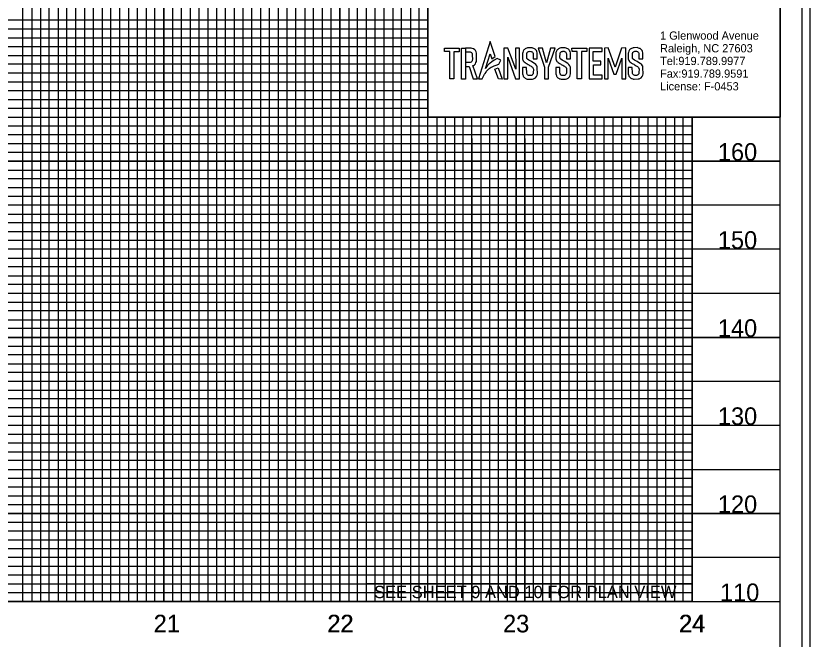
# Model space of a CAD drawing. Extents: x 1779926 to 1781610, y 602514 to 621564.
# Drawn here: x 1781159 to 1781610, y 603068.1 to 603422 of the extents above; entities that cross this region are included whole.
import ezdxf

# ---------------------------------------------------------------- set-up
doc = ezdxf.new("R2010")
doc.units = 0
for name, color, linetype in [('Exist Vertical Profile Horizontal Axis Label Major', 7, 'Continuous'), ('Exist Vertical Profile Vertical Axis Label', 7, 'Continuous'), ('Old_Level_2', 7, 'Continuous'), ('Old_Level_58', 7, 'Continuous'), ('Prop DSN Text', 7, 'Continuous'), ('Prop Grid Mask', 7, 'Continuous'), ('Scratch_Level_0', 7, 'Continuous'), ('Sheet DOT Grid CELL', 7, 'Continuous'), ('Sheet Layout Profile Border Port 1', 7, 'Continuous'), ('Sheet Plot Border Inside CELL', 7, 'Continuous'), ('Sheet Plot Border Outside CELL', 7, 'Continuous'), ('Sheet Profile CELL', 7, 'Continuous'), ('Sheet Profile Grid Major CELL', 7, 'Continuous'), ('Sheet Profile Grid Middle CELL', 7, 'Continuous'), ('Sheet Profile Grid Minor CELL', 7, 'Continuous')]:
    doc.layers.add(name, color=color, linetype=linetype)

msp = doc.modelspace()

# ---------------------------------------------------------------- linework, layer by layer
at = {"layer": 'Old_Level_2'}
for points in [[(1781428.25, 603407.49), (1781421.58, 603386.15), (1781423.81, 603386.16), (1781424.15, 603387), (1781424.72, 603388.16), (1781425.03, 603388.79), (1781425.41, 603389.33), (1781425.93, 603390.09), (1781426.26, 603390.56), (1781426.64, 603390.95), (1781427.02, 603391.34), (1781427.51, 603391.84), (1781427.92, 603392.11), (1781428.33, 603392.44), (1781428.89, 603392.76), (1781429.38, 603393.04), (1781430.6, 603393.61), (1781431.6, 603394.02), (1781433.24, 603394.58), (1781434.38, 603396.72), (1781432.2, 603397.68), (1781430.57, 603396.79), (1781429.19, 603395.89), (1781428.21, 603395.09), (1781427.69, 603394.67), (1781427.15, 603394.1), (1781426.62, 603393.53), (1781426.22, 603393.11), (1781425.84, 603392.46), (1781425.63, 603392.1), (1781428.26, 603400.48), (1781429.26, 603397.59), (1781431.16, 603398.84)], [(1781402.29, 603403.64), (1781410.75, 603403.65), (1781410.75, 603401.57), (1781407.64, 603401.57), (1781407.66, 603386.15), (1781405.31, 603386.15), (1781405.29, 603401.67), (1781402.32, 603401.67)], [(1781411.91, 603403.63), (1781414.22, 603403.64), (1781414.24, 603386.07), (1781411.92, 603386.07)], [(1781414.22, 603401.55), (1781416.61, 603401.55), (1781416.91, 603401.5), (1781417.32, 603401.34), (1781417.64, 603401.12), (1781417.87, 603400.85), (1781418.03, 603400.52), (1781418.15, 603400.26), (1781418.15, 603399.68), (1781418.16, 603397.19), (1781418.1, 603396.86), (1781418.01, 603396.42), (1781417.88, 603396.12), (1781417.68, 603395.86), (1781417.41, 603395.65), (1781416.99, 603395.5), (1781416.66, 603395.45), (1781416.34, 603395.41), (1781414.23, 603395.4), (1781414.24, 603393.29), (1781416.35, 603393.31), (1781418.72, 603386.14), (1781421.13, 603386.17), (1781418.48, 603393.71), (1781418.86, 603393.84), (1781419.4, 603394.24), (1781419.89, 603394.78), (1781420.23, 603395.41), (1781420.45, 603396.04), (1781420.43, 603396.23), (1781420.48, 603400.79), (1781420.27, 603401.54), (1781419.91, 603402.22), (1781419.5, 603402.69), (1781418.8, 603403.16), (1781418.12, 603403.39), (1781417.45, 603403.61), (1781417.04, 603403.61), (1781414.22, 603403.64)], [(1781436.02, 603403.67), (1781436.03, 603386.21), (1781438.27, 603386.21), (1781438.26, 603398.49), (1781442.71, 603386.19), (1781444.96, 603386.22), (1781444.94, 603403.72), (1781442.76, 603403.72), (1781442.78, 603391.74), (1781438.37, 603403.68)], [(1781452.72, 603397.5), (1781455.03, 603397.5), (1781455.02, 603400.98), (1781454.83, 603401.68), (1781454.55, 603402.27), (1781454.25, 603402.66), (1781453.88, 603403.02), (1781453.44, 603403.3), (1781453.01, 603403.47), (1781453.01, 603403.47), (1781452.55, 603403.67), (1781452.07, 603403.79), (1781451.75, 603403.87), (1781450, 603403.83), (1781449.47, 603403.74), (1781449.02, 603403.66), (1781448.55, 603403.42), (1781448.15, 603403.21), (1781447.76, 603402.93), (1781447.45, 603402.61), (1781447.2, 603402.25), (1781447.01, 603401.85), (1781446.75, 603401.16), (1781446.7, 603400.64), (1781446.7, 603397.47), (1781446.82, 603397), (1781447.05, 603396.5), (1781447.34, 603396.09), (1781447.63, 603395.78), (1781448.08, 603395.43), (1781448.54, 603395.09), (1781448.82, 603394.87), (1781449.3, 603394.64), (1781449.79, 603394.42), (1781450.18, 603394.16), (1781450.62, 603393.88), (1781451.15, 603393.61), (1781451.58, 603393.39), (1781452.01, 603393.08), (1781452.32, 603392.78), (1781452.57, 603392.54), (1781452.72, 603392.06), (1781452.82, 603391.76), (1781452.78, 603389.53), (1781452.62, 603389.04), (1781452.38, 603388.62), (1781452.05, 603388.33), (1781451.69, 603388.17), (1781451.35, 603388.1), (1781450.39, 603388.08), (1781450.07, 603388.17), (1781449.74, 603388.36), (1781449.41, 603388.56), (1781449.27, 603388.89), (1781449.13, 603389.23), (1781449.01, 603389.49), (1781448.98, 603392.61), (1781446.64, 603392.58), (1781446.68, 603388.87), (1781446.8, 603388.59), (1781447.07, 603387.72), (1781447.24, 603387.43), (1781447.5, 603387.11), (1781447.88, 603386.74), (1781448.18, 603386.55), (1781448.62, 603386.36), (1781448.78, 603386.3), (1781449.2, 603386.12), (1781449.74, 603386.06), (1781450.13, 603386.02), (1781452.27, 603386.08), (1781452.87, 603386.22), (1781453.69, 603386.59), (1781453.97, 603386.72), (1781454.6, 603387.51), (1781454.93, 603388.3), (1781455.08, 603389.01), (1781455.03, 603392.43), (1781455.02, 603392.9), (1781454.89, 603393.28), (1781454.7, 603393.63), (1781454.16, 603394.39), (1781453.45, 603394.95), (1781452.48, 603395.53), (1781451.73, 603395.97), (1781450.27, 603396.74), (1781449.52, 603397.3), (1781449.19, 603397.72), (1781449.11, 603398), (1781449.03, 603398.29), (1781449.08, 603400.72), (1781449.2, 603400.97), (1781449.33, 603401.23), (1781449.51, 603401.38), (1781449.74, 603401.58), (1781450, 603401.68), (1781450.25, 603401.79), (1781450.4, 603401.76), (1781450.42, 603401.84), (1781451.38, 603401.82), (1781451.65, 603401.71), (1781451.93, 603401.6), (1781452.21, 603401.49), (1781452.34, 603401.3), (1781452.52, 603401.02), (1781452.61, 603400.74), (1781452.71, 603400.47), (1781452.7, 603400.16)], [(1781457.99, 603403.68), (1781455.45, 603403.68), (1781459.07, 603392.8), (1781459.1, 603386.25), (1781461.49, 603386.27), (1781461.46, 603392.76), (1781465.12, 603403.72), (1781462.62, 603403.65), (1781460.31, 603395.31)], [(1781471.59, 603397.52), (1781473.9, 603397.52), (1781473.89, 603401), (1781473.7, 603401.7), (1781473.42, 603402.29), (1781473.12, 603402.68), (1781472.75, 603403.03), (1781472.31, 603403.32), (1781471.88, 603403.49), (1781471.88, 603403.49), (1781471.43, 603403.68), (1781470.94, 603403.81), (1781470.62, 603403.89), (1781468.87, 603403.85), (1781468.34, 603403.76), (1781467.89, 603403.68), (1781467.43, 603403.44), (1781467.02, 603403.23), (1781466.63, 603402.94), (1781466.32, 603402.63), (1781466.08, 603402.27), (1781465.88, 603401.87), (1781465.63, 603401.17), (1781465.58, 603400.66), (1781465.58, 603397.49), (1781465.69, 603397.01), (1781465.92, 603396.52), (1781466.21, 603396.11), (1781466.51, 603395.8), (1781466.96, 603395.45), (1781467.41, 603395.1), (1781467.69, 603394.88), (1781468.18, 603394.66), (1781468.66, 603394.43), (1781469.05, 603394.18), (1781469.49, 603393.89), (1781470.02, 603393.63), (1781470.45, 603393.41), (1781470.88, 603393.09), (1781471.19, 603392.8), (1781471.44, 603392.56), (1781471.59, 603392.08), (1781471.69, 603391.78), (1781471.65, 603389.54), (1781471.49, 603389.06), (1781471.25, 603388.64), (1781470.92, 603388.35), (1781470.56, 603388.19), (1781470.22, 603388.12), (1781469.26, 603388.1), (1781468.94, 603388.19), (1781468.61, 603388.38), (1781468.28, 603388.57), (1781468.14, 603388.91), (1781468, 603389.24), (1781467.88, 603389.51), (1781467.85, 603392.62), (1781465.51, 603392.6), (1781465.55, 603388.89), (1781465.67, 603388.6), (1781465.94, 603387.74), (1781466.12, 603387.45), (1781466.37, 603387.13), (1781466.75, 603386.76), (1781467.05, 603386.56), (1781467.49, 603386.38), (1781467.65, 603386.31), (1781468.08, 603386.13), (1781468.61, 603386.08), (1781469, 603386.04), (1781471.15, 603386.1), (1781471.74, 603386.24), (1781472.57, 603386.61), (1781472.85, 603386.74), (1781473.47, 603387.53), (1781473.8, 603388.31), (1781473.96, 603389.02), (1781473.9, 603392.45), (1781473.9, 603392.92), (1781473.76, 603393.29), (1781473.57, 603393.65), (1781473.03, 603394.41), (1781472.33, 603394.96), (1781471.35, 603395.54), (1781470.61, 603395.99), (1781469.14, 603396.75), (1781468.39, 603397.32), (1781468.06, 603397.74), (1781467.98, 603398.02), (1781467.91, 603398.31), (1781467.95, 603400.74), (1781468.08, 603400.99), (1781468.2, 603401.25), (1781468.38, 603401.4), (1781468.61, 603401.59), (1781468.87, 603401.7), (1781469.13, 603401.81), (1781469.27, 603401.78), (1781469.29, 603401.85), (1781470.25, 603401.84), (1781470.52, 603401.73), (1781470.8, 603401.62), (1781471.08, 603401.51), (1781471.21, 603401.32), (1781471.39, 603401.04), (1781471.49, 603400.76), (1781471.58, 603400.49), (1781471.57, 603400.18)], [(1781474.74, 603403.71), (1781483.21, 603403.71), (1781483.21, 603401.64), (1781480.1, 603401.64), (1781480.12, 603386.22), (1781477.77, 603386.21), (1781477.75, 603401.74), (1781474.78, 603401.74)], [(1781491.82, 603403.71), (1781484.43, 603403.71), (1781484.45, 603386.28), (1781491.92, 603386.29), (1781491.92, 603388.26), (1781486.87, 603388.25), (1781486.87, 603394.1), (1781491.08, 603394.1), (1781491.08, 603396.17), (1781486.83, 603396.17), (1781486.83, 603401.67), (1781491.84, 603401.67)], [(1781499.19, 603392.86), (1781495.38, 603403.79), (1781493.17, 603403.68), (1781493.25, 603386.22), (1781495.36, 603386.23), (1781495.31, 603397.91), (1781498.57, 603388.92), (1781499.92, 603388.89), (1781502.99, 603398.02), (1781503.03, 603386.3), (1781505.32, 603386.31), (1781505.25, 603403.73), (1781502.95, 603403.72)], [(1781512.72, 603397.56), (1781515.03, 603397.56), (1781515.03, 603401.03), (1781514.83, 603401.74), (1781514.55, 603402.33), (1781514.25, 603402.72), (1781513.88, 603403.07), (1781513.44, 603403.35), (1781513.02, 603403.53), (1781513.02, 603403.53), (1781512.56, 603403.72), (1781512.08, 603403.84), (1781511.76, 603403.92), (1781510.01, 603403.89), (1781509.48, 603403.8), (1781509.02, 603403.72), (1781508.56, 603403.48), (1781508.15, 603403.27), (1781507.76, 603402.98), (1781507.45, 603402.67), (1781507.21, 603402.3), (1781507.01, 603401.91), (1781506.76, 603401.21), (1781506.71, 603400.7), (1781506.71, 603397.53), (1781506.82, 603397.05), (1781507.05, 603396.56), (1781507.34, 603396.15), (1781507.64, 603395.84), (1781508.09, 603395.49), (1781508.54, 603395.14), (1781508.83, 603394.92), (1781509.31, 603394.7), (1781509.79, 603394.47), (1781510.18, 603394.22), (1781510.62, 603393.93), (1781511.15, 603393.67), (1781511.58, 603393.45), (1781512.01, 603393.13), (1781512.32, 603392.84), (1781512.57, 603392.6), (1781512.73, 603392.12), (1781512.82, 603391.82), (1781512.79, 603389.58), (1781512.62, 603389.1), (1781512.38, 603388.68), (1781512.05, 603388.39), (1781511.7, 603388.23), (1781511.36, 603388.16), (1781510.39, 603388.14), (1781510.07, 603388.23), (1781509.74, 603388.42), (1781509.41, 603388.61), (1781509.27, 603388.95), (1781509.13, 603389.28), (1781509.02, 603389.55), (1781508.98, 603392.66), (1781506.64, 603392.63), (1781506.69, 603388.92), (1781506.8, 603388.64), (1781507.07, 603387.78), (1781507.25, 603387.49), (1781507.5, 603387.17), (1781507.88, 603386.79), (1781508.19, 603386.6), (1781508.62, 603386.42), (1781508.78, 603386.35), (1781509.21, 603386.17), (1781509.74, 603386.12), (1781510.14, 603386.08), (1781512.28, 603386.13), (1781512.87, 603386.27), (1781513.7, 603386.65), (1781513.98, 603386.77), (1781514.6, 603387.57), (1781514.93, 603388.35), (1781515.09, 603389.06), (1781515.04, 603392.48), (1781515.03, 603392.96), (1781514.9, 603393.33), (1781514.71, 603393.69), (1781514.17, 603394.45), (1781513.46, 603395), (1781512.48, 603395.58), (1781511.74, 603396.03), (1781510.28, 603396.79), (1781509.52, 603397.35), (1781509.19, 603397.78), (1781509.12, 603398.06), (1781509.04, 603398.34), (1781509.08, 603400.77), (1781509.21, 603401.03), (1781509.33, 603401.28), (1781509.51, 603401.44), (1781509.74, 603401.63), (1781510, 603401.74), (1781510.26, 603401.85), (1781510.41, 603401.82), (1781510.42, 603401.89), (1781511.38, 603401.88), (1781511.66, 603401.77), (1781511.93, 603401.66), (1781512.21, 603401.55), (1781512.34, 603401.35), (1781512.53, 603401.08), (1781512.62, 603400.8), (1781512.71, 603400.52), (1781512.7, 603400.22)], [(1781430.86, 603391.78), (1781432.78, 603392.55), (1781435.04, 603386.11), (1781432.94, 603386.19)]]:
    msp.add_lwpolyline(points, close=True, dxfattribs=at)
at = {"layer": 'Old_Level_58'}
msp.add_lwpolyline([(1781392.96, 603428.4), (1781592.95, 603428.4), (1781592.95, 603364.45), (1781392.96, 603364.45)], close=True, dxfattribs=at)
at = {"layer": 'Prop Grid Mask'}
msp.add_lwpolyline([(1781542.96, 603099.45), (1781357.96, 603099.45), (1781357.96, 603089.45), (1781542.96, 603089.45)], close=True, dxfattribs=at)
at = {"layer": 'Scratch_Level_0'}
msp.add_lwpolyline([(1780142.96, 603089.44), (1780142.96, 603589.44), (1781392.96, 603589.44), (1781392.96, 603364.44), (1781542.96, 603364.44), (1781542.96, 603089.44)], close=True, dxfattribs=at)
at = {"layer": 'Sheet DOT Grid CELL'}
for p, q in [((1781192.96, 603089.45), (1781192.96, 603589.45)), ((1781242.96, 603089.45), (1781242.96, 603589.45)), ((1781292.96, 603089.45), (1781292.96, 603589.45)), ((1781342.96, 603089.45), (1781342.96, 603589.45)), ((1781392.96, 603089.45), (1781392.96, 603451.9)), ((1781392.91, 603389.45), (1780092.96, 603389.45)), ((1781442.96, 603089.45), (1781442.96, 603364.45)), ((1781492.96, 603089.45), (1781492.96, 603364.45)), ((1781542.96, 603089.45), (1781542.96, 603364.45)), ((1781592.96, 603339.45), (1780092.96, 603339.45)), ((1781592.96, 603289.45), (1780092.96, 603289.45)), ((1781592.96, 603239.45), (1780092.96, 603239.45)), ((1781592.96, 603189.45), (1780092.96, 603189.45)), ((1781592.96, 603139.45), (1780092.96, 603139.45))]:
    msp.add_line(p, q, dxfattribs=at)
at = {"layer": 'Sheet Layout Profile Border Port 1'}
msp.add_lwpolyline([(1780142.96, 603589.44), (1781392.91, 603589.45), (1781392.9, 603364.45), (1781542.96, 603364.44), (1781542.96, 603089.45), (1780142.96, 603089.44)], close=True, dxfattribs=at)
msp.add_lwpolyline([(1780142.96, 603428.4), (1780142.96, 603089.45), (1781542.96, 603089.45), (1781542.96, 603364.45)], dxfattribs=at)
at = {"layer": 'Sheet Plot Border Inside CELL'}
msp.add_lwpolyline([(1779938.96, 602536.9), (1781605.46, 602536.9), (1781605.46, 603592), (1779938.96, 603592)], close=True, dxfattribs=at)
at = {"layer": 'Sheet Plot Border Outside CELL'}
msp.add_lwpolyline([(1779925.96, 602514.45), (1781609.96, 602514.45), (1781609.96, 603614.45), (1779925.96, 603614.45)], close=True, dxfattribs=at)
at = {"layer": 'Sheet Profile CELL'}
msp.add_line((1780092.96, 603089.45), (1781592.96, 603089.45), dxfattribs=at)
msp.add_lwpolyline([(1781592.96, 603589.45), (1780092.96, 603589.45), (1780092.96, 602539.45), (1781592.96, 602539.45)], close=True, dxfattribs=at)
at = {"layer": 'Sheet Profile Grid Major CELL'}
for points in [[(1781142.96, 603089.45), (1781192.96, 603089.45), (1781192.96, 603589.45), (1781242.96, 603589.45), (1781242.96, 603089.45), (1781292.96, 603089.45), (1781292.96, 603589.45), (1781342.96, 603589.45), (1781342.96, 603089.45), (1781392.96, 603089.45), (1781392.96, 603589.45), (1781419.26, 603589.45)], [(1781542.96, 603364.45), (1781542.96, 603089.45), (1781592.96, 603089.45), (1781592.96, 603439.45)], [(1781392.91, 603389.45), (1780092.96, 603389.45), (1780092.96, 603339.45), (1781592.96, 603339.45)], [(1781442.96, 603364.45), (1781442.96, 603089.45), (1781492.96, 603089.45), (1781492.96, 603089.45), (1781492.96, 603364.45)], [(1781592.96, 603289.45), (1780092.96, 603289.45), (1780092.96, 603239.45), (1781592.96, 603239.45)], [(1781592.96, 603189.45), (1780092.96, 603189.45), (1780092.96, 603189.45), (1780092.96, 603139.45), (1781592.96, 603139.45)]]:
    msp.add_lwpolyline(points, dxfattribs=at)
at = {"layer": 'Sheet Profile Grid Middle CELL'}
for points in [[(1781117.96, 603589.45), (1781167.96, 603589.45), (1781167.96, 603089.45), (1781217.96, 603089.45), (1781217.96, 603589.45), (1781267.96, 603589.45), (1781267.96, 603089.45), (1781317.96, 603089.45), (1781317.96, 603589.45), (1781367.96, 603589.45), (1781367.96, 603089.45), (1781417.96, 603089.45), (1781417.96, 603364.45)], [(1781392.91, 603414.45), (1780092.96, 603414.45), (1780092.96, 603364.45), (1781417.96, 603364.45)], [(1781417.96, 603364.45), (1781592.96, 603364.45)], [(1781417.96, 603352.25), (1781417.96, 603089.45), (1781467.96, 603089.45), (1781467.96, 603364.45)], [(1781467.96, 603352.25), (1781467.96, 603089.45), (1781517.96, 603089.45), (1781517.96, 603364.45)], [(1781592.96, 603314.45), (1780092.96, 603314.45), (1780092.96, 603264.45), (1781592.96, 603264.45)], [(1781592.96, 603214.45), (1780092.96, 603214.45), (1780092.96, 603164.45), (1781592.96, 603164.45)], [(1781592.96, 603114.45), (1780092.96, 603114.45)]]:
    msp.add_lwpolyline(points, dxfattribs=at)
at = {"layer": 'Sheet Profile Grid Minor CELL'}
for p, q in [((1781392.96, 603404.45), (1780142.96, 603404.45)), ((1780142.96, 603399.45), (1781392.96, 603399.45)), ((1781392.91, 603379.45), (1780142.96, 603379.45)), ((1780142.96, 603374.45), (1781392.91, 603374.45)), ((1781542.96, 603354.45), (1780142.96, 603354.45)), ((1780142.96, 603349.45), (1781542.96, 603349.45)), ((1781542.96, 603344.45), (1780142.96, 603344.45)), ((1780142.96, 603334.45), (1781542.96, 603334.45)), ((1781542.96, 603329.45), (1780142.96, 603329.45)), ((1780142.96, 603324.45), (1781542.96, 603324.45)), ((1781542.96, 603319.45), (1780142.96, 603319.45)), ((1780142.96, 603309.45), (1781542.96, 603309.45)), ((1781542.96, 603304.45), (1780142.96, 603304.45)), ((1780142.96, 603299.45), (1781542.96, 603299.45)), ((1781542.96, 603294.45), (1780142.96, 603294.45)), ((1780142.96, 603284.45), (1781542.96, 603284.45)), ((1781542.96, 603279.45), (1780142.96, 603279.45)), ((1780142.96, 603274.45), (1781542.96, 603274.45)), ((1781542.96, 603269.45), (1780142.96, 603269.45)), ((1780142.96, 603259.45), (1781542.96, 603259.45)), ((1781542.96, 603254.45), (1780142.96, 603254.45)), ((1780142.96, 603249.45), (1781542.96, 603249.45)), ((1781542.96, 603244.45), (1780142.96, 603244.45)), ((1780142.96, 603234.45), (1781542.96, 603234.45)), ((1781542.96, 603229.45), (1780142.96, 603229.45)), ((1780142.96, 603224.45), (1781542.96, 603224.45)), ((1781542.96, 603219.45), (1780142.96, 603219.45)), ((1780142.96, 603209.45), (1781542.96, 603209.45)), ((1781542.96, 603204.45), (1780142.96, 603204.45)), ((1781542.96, 603199.45), (1780142.96, 603199.45)), ((1781542.96, 603194.45), (1780142.96, 603194.45)), ((1780142.96, 603184.45), (1781542.96, 603184.45)), ((1781542.96, 603179.45), (1780142.96, 603179.45)), ((1780142.96, 603174.45), (1781542.96, 603174.45)), ((1781542.96, 603169.45), (1780142.96, 603169.45)), ((1780142.96, 603159.45), (1781542.96, 603159.45)), ((1781542.96, 603154.45), (1780142.96, 603154.45)), ((1780142.96, 603149.45), (1781542.96, 603149.45)), ((1781542.96, 603144.45), (1780142.96, 603144.45)), ((1780142.96, 603134.45), (1781542.96, 603134.45)), ((1781542.96, 603129.45), (1780142.96, 603129.45)), ((1780142.96, 603124.45), (1781542.96, 603124.45)), ((1781542.96, 603119.45), (1780142.96, 603119.45)), ((1780142.96, 603109.45), (1781542.96, 603109.45)), ((1781542.96, 603104.45), (1780142.96, 603104.45)), ((1780142.96, 603099.45), (1781542.96, 603099.45))]:
    msp.add_line(p, q, dxfattribs=at)
for points in [[(1781157.96, 603089.45), (1781162.96, 603089.45), (1781162.96, 603589.45)], [(1781172.96, 603589.45), (1781172.96, 603089.45), (1781177.96, 603089.45), (1781177.96, 603589.45)], [(1781182.96, 603589.45), (1781182.96, 603089.45), (1781187.96, 603089.45), (1781187.96, 603589.45)], [(1781197.96, 603589.45), (1781197.96, 603089.45), (1781202.96, 603089.45), (1781202.96, 603589.45)], [(1781207.96, 603589.45), (1781207.96, 603089.45), (1781212.96, 603089.45), (1781212.96, 603589.45)], [(1781222.96, 603589.45), (1781222.96, 603089.45), (1781227.96, 603089.45), (1781227.96, 603589.45)], [(1781232.96, 603589.45), (1781232.96, 603089.45), (1781237.96, 603089.45), (1781237.96, 603589.45)], [(1781247.96, 603589.45), (1781247.96, 603089.45), (1781252.96, 603089.45), (1781252.96, 603589.45)], [(1781257.96, 603589.45), (1781257.96, 603089.45), (1781262.96, 603089.45), (1781262.96, 603589.45)], [(1781272.96, 603589.45), (1781272.96, 603089.45), (1781277.96, 603089.45), (1781277.96, 603589.45)], [(1781282.96, 603589.45), (1781282.96, 603089.45)], [(1781282.96, 603089.45), (1781287.96, 603089.45), (1781287.96, 603589.45)], [(1781297.96, 603589.45), (1781297.96, 603089.45), (1781302.96, 603089.45), (1781302.96, 603589.45)], [(1781307.96, 603589.45), (1781307.96, 603089.45), (1781312.96, 603089.45), (1781312.96, 603589.45)], [(1781322.96, 603589.45), (1781322.96, 603089.45), (1781327.96, 603089.45), (1781327.96, 603589.45)], [(1781332.96, 603589.45), (1781332.96, 603089.45), (1781337.96, 603089.45), (1781337.96, 603589.45)], [(1781347.96, 603589.45), (1781347.96, 603089.45), (1781352.96, 603089.45), (1781352.96, 603589.45)], [(1781357.96, 603589.45), (1781357.96, 603089.45), (1781362.96, 603089.45), (1781362.96, 603589.45)], [(1781372.96, 603589.45), (1781372.96, 603089.45), (1781377.96, 603089.45), (1781377.96, 603589.45)], [(1781382.96, 603589.45), (1781382.96, 603089.45), (1781387.96, 603089.45), (1781387.96, 603589.45)], [(1781392.91, 603419.45), (1780142.96, 603419.45), (1780142.96, 603409.45), (1781392.91, 603409.45)], [(1781392.91, 603394.45), (1780142.96, 603394.45), (1780142.96, 603384.45), (1781392.91, 603384.45)], [(1781392.91, 603369.45), (1780142.96, 603369.45), (1780142.96, 603359.45), (1781542.96, 603359.45)], [(1781397.96, 603364.45), (1781397.96, 603089.45), (1781402.96, 603089.45), (1781402.96, 603364.45)], [(1781407.96, 603364.45), (1781407.96, 603089.45), (1781412.96, 603089.45), (1781412.96, 603364.45)], [(1781422.96, 603364.45), (1781422.96, 603089.45), (1781422.96, 603089.45), (1781427.96, 603089.45), (1781432.96, 603089.45), (1781432.96, 603364.45)], [(1781427.96, 603364.45), (1781427.96, 603089.45)], [(1781437.94, 603364.45), (1781437.86, 603089.5), (1781442.86, 603089.5), (1781447.96, 603089.45), (1781447.96, 603364.45)], [(1781447.96, 603352.25), (1781447.96, 603089.45), (1781452.96, 603089.45), (1781452.96, 603364.45)], [(1781457.96, 603364.45), (1781457.96, 603089.45), (1781462.96, 603089.45), (1781462.96, 603364.45)], [(1781472.96, 603364.45), (1781472.96, 603089.45), (1781477.96, 603089.45), (1781477.96, 603364.45)], [(1781482.96, 603364.45), (1781482.96, 603089.45), (1781487.96, 603089.45), (1781487.96, 603364.45)], [(1781497.96, 603364.45), (1781497.96, 603089.45), (1781502.96, 603089.45), (1781502.96, 603364.45)], [(1781507.96, 603364.45), (1781507.96, 603089.45), (1781512.96, 603089.45), (1781512.96, 603364.45)], [(1781522.96, 603364.45), (1781522.96, 603089.45), (1781527.96, 603089.45), (1781527.96, 603364.45)], [(1781532.96, 603364.45), (1781532.96, 603089.45), (1781537.96, 603089.45), (1781537.96, 603364.45)], [(1781542.96, 603094.45), (1780142.96, 603094.45)]]:
    msp.add_lwpolyline(points, dxfattribs=at)

# ---------------------------------------------------------------- texts
at = {"layer": 'Exist Vertical Profile Horizontal Axis Label Major'}
for s, p in [('21', (1781237.19, 603071.95)), ('21', (1781237.28, 603071.95)), ('21', (1781237.28, 603071.95)), ('22', (1781335.73, 603071.95)), ('22', (1781335.96, 603071.95)), ('22', (1781335.96, 603071.95)), ('23', (1781435.57, 603071.95)), ('23', (1781435.63, 603071.95)), ('23', (1781435.63, 603071.95)), ('24', (1781535.41, 603071.95)), ('24', (1781535.69, 603071.95)), ('24', (1781535.69, 603071.95))]:
    msp.add_text(s, height=10, dxfattribs=at).set_placement(p)
at = {"layer": 'Exist Vertical Profile Vertical Axis Label'}
for s, p in [('160', (1781557.59, 603339.7)), ('150', (1781557.59, 603289.7)), ('140', (1781557.59, 603239.7)), ('130', (1781557.59, 603189.7)), ('120', (1781557.59, 603139.7)), ('110', (1781558.79, 603089.7))]:
    msp.add_text(s, height=10, dxfattribs=at).set_placement(p)
at = {"layer": 'Old_Level_2'}
for s, p in [('1 Glenwood Avenue', (1781524.75, 603408.44)), ('Raleigh, NC 27603', (1781524.75, 603401.24)), ('Tel:919.789.9977 ', (1781524.75, 603394.05)), ('Fax:919.789.9591', (1781524.75, 603386.85)), ('License: F-0453', (1781524.75, 603379.65))]:
    msp.add_text(s, height=4.6576, rotation=360, dxfattribs=at).set_placement(p)
at = {"layer": 'Prop DSN Text'}
msp.add_text('SEE SHEET 9 AND 10 FOR PLAN VIEW', height=7, dxfattribs=at).set_placement((1781362.39, 603091.4))

doc.saveas('drawing.dxf')
